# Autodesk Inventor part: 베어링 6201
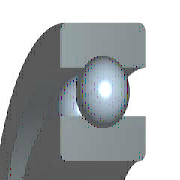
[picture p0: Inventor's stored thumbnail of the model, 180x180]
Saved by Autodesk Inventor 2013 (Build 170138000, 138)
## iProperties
Created: 2009-02
Part Number: 베어링 6201
Material: 강, 연강
Description: 깊은 그루브 볼 베어링
Document SubType Name: Modeling
Standard: KS B 2023
Designer: KYOUNG IL JANG
Standards Organization: KS
Language: ko-KR
Size Designation: 6201 - 12 x 32 x 10
Categories: <MemberInstance><Categories><Category DisplayName="샤프트 부품" InternalName="7f7aeb1f-a693-4053-b835-cee3144e0d98" Mnemonic="SHFT"><Category DisplayName="베어링" Inter
Density: 7.86 g/cm^3
Mass: 36.8026 g
Surface Area: 42.5728 cm^2
Volume: 4.68226 cm^3
Vendor: CBT Solutions
Company: 한국ATC센터
IsCustomPart: 1
Author: KYOUNG IL JANG
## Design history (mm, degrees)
sketch "스케치" dims "d0" = 5.2 (= -0.26 x WD + 0.26 x BD)
  geometry: L1 (2.4, 11)-(7.6, 11); L2 (5, 11)-(5, 8.4); L3 (5, 11)-(5, 13.6); L4 (3.068, 9.26)-(0, 9.26); L5 (0, 6)-(10, 6); L6 (3.068, 12.74)-(0, 12.74); L7 (0, 16)-(10, 16); L8 (10, 6)-(10, 9.26); L9 (6.932, 9.26)-(10, 9.26); L10 (6.932, 12.74)-(10, 12.74); L11 (10, 16)-(10, 12.74); L12 (-1.4, 0)-(8.4, 0) reference; L13 (0, -0.3)-(0, 5.3) reference
  constraints: 22 end point, 4 point on line, 2 collinear, 2 perpendicular, 2 symmetric about line, 1 midpoint, 1 parallel, 14 other
  dimensions: "d9" = 12 diameter of L5 L12 (= WD); "d11" = 32 diameter of L7 L12 (= BD); "d12" = 10 distance between parallel lines of L8 L13 (= KB); "d13" = 18.52 diameter of L9 L12 (= 0.326 x BD + 0.674 x WD)
revolve "본체" stored, may be unused: angle "d6" = 90 deg
revolve "볼" stored, may be unused: angle "d7" = 90 deg
pattern_circular "IDS_ARRAYBALL[SIMPL:T]" dims angle "d3" = 360 deg
body "Solid1"
fillet "모깎기1" dims "d1" = 0.6 (= KRS)
other parameters: "WD" = 12 [user parameter; used in 5 equation terms], "BD" = 32 [user parameter; used in 5 equation terms], "KB" = 10 [user parameter; used in 1 equation term], "KRS" = 0.6 [user parameter; used in 1 equation term], "d4" = 0, "d5" = 0, "d8" = 0, "d14" = 0, "d15" = 0, "BBA" = 0 [user parameter], "BC0" = 3100000 [user parameter], "BC" = 6890000 [user parameter], "BR" = 16 (= 0.5 x BD) [user parameter], "WR" = 6 (= 0.5 x WD) [user parameter]
